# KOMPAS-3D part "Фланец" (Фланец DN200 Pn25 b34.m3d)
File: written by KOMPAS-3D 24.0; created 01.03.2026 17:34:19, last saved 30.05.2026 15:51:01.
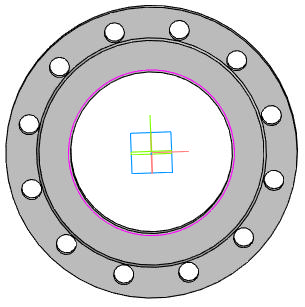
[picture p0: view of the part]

Document properties: Автор: R2D2; Полное имя файла: E:\Работа\Зайцев\GVWR2434M-2W-F-ОСТ Задвижка клиновая с выдвижным штоком DN.ru Ду50-300 Ру25\исходные материалы\DN200\Фланец DN200 Pn25 b34.m3d

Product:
- Part/product: Фланец
    Масса: 16.424725
    additional columns: Типовые

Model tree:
1. Эскиз:2
2. Элемент вращения:1
     Угол 1 = 360
3. Эскиз:3  (with: Грань.Элемент вращения:1)
4. Элемент выдавливания:2
     Расстояние 1 = 3; Расстояние 2 = 31
5. Массив по концентрической сетке:1  (with: Элемент выдавливания:2, Эскиз:3, Грань.Элемент вращения:1)  (12 pattern instances)
     Шаг 2 = 360
6. Эскиз:4  (with: Грань.Элемент вращения:1)
7. Элемент выдавливания:3
     Расстояние 2 = 4

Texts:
  Линейный размер с обрывом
